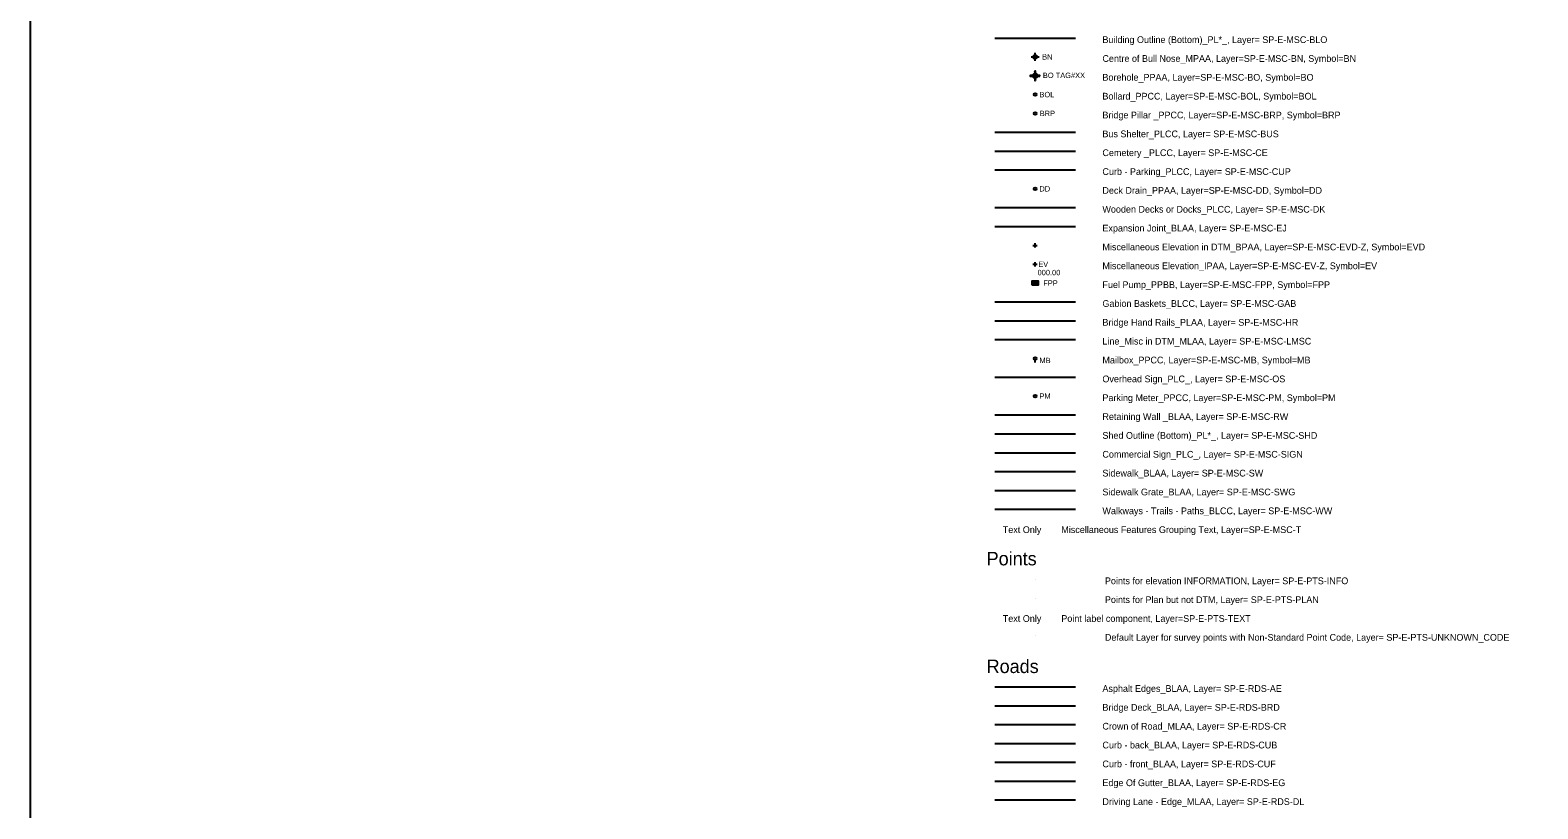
# Model space of a CAD drawing. Extents: x 500528 to 502626, y 4210261 to 4212624.
# Drawn here: x 500528 to 501088, y 4211439 to 4211729 of the extents above; entities that cross this region are included whole.
import ezdxf

# ---------------------------------------------------------------- set-up
doc = ezdxf.new("R2010")
doc.units = 0
for name, color, linetype in [('Default', 7, 'Continuous'), ('SP-E-MSC-BLO', 7, 'Continuous'), ('SP-E-MSC-BN', 7, 'Continuous'), ('SP-E-MSC-BO', 7, 'Continuous'), ('SP-E-MSC-BOL', 7, 'Continuous'), ('SP-E-MSC-BRP', 7, 'Continuous'), ('SP-E-MSC-BUS', 7, 'Continuous'), ('SP-E-MSC-CE', 7, 'Continuous'), ('SP-E-MSC-CUP', 7, 'Continuous'), ('SP-E-MSC-DD', 7, 'Continuous'), ('SP-E-MSC-DK', 7, 'Continuous'), ('SP-E-MSC-EJ', 7, 'Continuous'), ('SP-E-MSC-EV-Z', 7, 'Continuous'), ('SP-E-MSC-EVD-Z', 7, 'Continuous'), ('SP-E-MSC-FPP', 7, 'Continuous'), ('SP-E-MSC-GAB', 7, 'Continuous'), ('SP-E-MSC-HR', 7, 'Continuous'), ('SP-E-MSC-LMSC', 7, 'Continuous'), ('SP-E-MSC-MB', 7, 'Continuous'), ('SP-E-MSC-OS', 7, 'Continuous'), ('SP-E-MSC-PM', 7, 'Continuous'), ('SP-E-MSC-RW', 7, 'Continuous'), ('SP-E-MSC-SHD', 7, 'Continuous'), ('SP-E-MSC-SIGN', 7, 'Continuous'), ('SP-E-MSC-SW', 7, 'Continuous'), ('SP-E-MSC-SWG', 7, 'Continuous'), ('SP-E-MSC-T', 7, 'Continuous'), ('SP-E-MSC-WW', 7, 'Continuous'), ('SP-E-PTS-INFO', 7, 'Continuous'), ('SP-E-PTS-PLAN', 7, 'Continuous'), ('SP-E-PTS-TEXT', 7, 'Continuous'), ('SP-E-PTS-UNKNOWN_CODE', 7, 'Continuous'), ('SP-E-RDS-AE', 7, 'Continuous'), ('SP-E-RDS-BRD', 7, 'Continuous'), ('SP-E-RDS-CR', 7, 'Continuous'), ('SP-E-RDS-CUB', 7, 'Continuous'), ('SP-E-RDS-CUF', 7, 'Continuous'), ('SP-E-RDS-DL', 7, 'Continuous'), ('SP-E-RDS-EG', 7, 'Continuous')]:
    doc.layers.add(name, color=color, linetype=linetype)

# ---------------------------------------------------------------- blocks, each defined once
blk = doc.blocks.new('POINT_DISPLAY')
at = {"layer": 'Default'}
blk.add_line((0, 0), (0, 0), dxfattribs=at)
blk = doc.blocks.new('BN')
at = {"layer": 'SP-E-MSC-T'}
for points in [[(-0.15, 0), (0.15, 0)], [(0, -0.15), (0, 0.15)]]:
    blk.add_lwpolyline(points, dxfattribs=at)
blk.add_circle((0, 0), 0.075, dxfattribs=at)
at = {"layer": 'SP-E-MSC-BN'}
blk.add_blockref('POINT_DISPLAY', (0, 0), dxfattribs=at)
at = {"layer": 'SP-E-MSC-T'}
blk.add_text('BN', height=0.2, dxfattribs=at).set_placement((0.262, -0.1))
blk = doc.blocks.new('BO')
at = {"layer": 'SP-E-MSC-BO'}
for points in [[(0.174, 0.011), (-0.18, 0.011)], [(-0.18, 0.011), (-0.18, -0.011)], [(-0.087, 0.005), (-0.18, 0.011), (-0.18, 0.005), (-0.087, 0.005)], [(-0.087, 0.005), (-0.086, 0.011), (-0.18, 0.011), (-0.087, 0.005)], [(-0.087, 0), (-0.18, 0.005), (-0.18, 0), (-0.087, 0)], [(-0.087, 0), (-0.087, 0.005), (-0.18, 0.005), (-0.087, 0)], [(-0.087, -0.005), (-0.18, 0), (-0.18, -0.005), (-0.087, -0.005)], [(-0.087, -0.005), (-0.087, 0), (-0.18, 0), (-0.087, -0.005)], [(0.011, 0.166), (-0.011, 0.166)], [(-0.011, 0.166), (-0.011, -0.174)], [(0.011, 0.087), (-0.011, 0.166), (-0.011, 0.087), (0.011, 0.087)], [(0.011, 0.087), (0.011, 0.166), (-0.011, 0.166), (0.011, 0.087)], [(-0.011, 0.086), (0, 0.087), (-0.011, 0.087), (-0.011, 0.086)], [(0.011, 0.086), (0.011, 0.087), (0, 0.087), (0.011, 0.086)], [(0, 0), (0, 0)], [(0.011, -0.174), (0.011, 0.166)], [(0.174, 0.005), (0.086, 0.011), (0.087, 0.005), (0.174, 0.005)], [(0.174, 0.005), (0.174, 0.011), (0.086, 0.011), (0.174, 0.005)], [(0.174, 0), (0.087, 0.005), (0.087, 0), (0.174, 0)], [(0.174, 0), (0.174, 0.005), (0.087, 0.005), (0.174, 0)], [(0.174, -0.005), (0.087, 0), (0.087, -0.005), (0.174, -0.005)], [(0.174, -0.005), (0.174, 0), (0.087, 0), (0.174, -0.005)], [(0.174, -0.011), (0.174, 0.011)], [(-0.086, -0.011), (-0.18, -0.005), (-0.18, -0.011), (-0.086, -0.011)], [(-0.086, -0.011), (-0.087, -0.005), (-0.18, -0.005), (-0.086, -0.011)], [(-0.18, -0.011), (0.174, -0.011)], [(0, -0.087), (-0.011, -0.086), (-0.011, -0.087), (0, -0.087)], [(0.011, -0.174), (-0.011, -0.087), (-0.011, -0.174), (0.011, -0.174)], [(0.011, -0.174), (0.011, -0.087), (-0.011, -0.087), (0.011, -0.174)], [(-0.011, -0.174), (0.011, -0.174)], [(0.011, -0.087), (0.011, -0.086), (0, -0.087), (0.011, -0.087)], [(0.174, -0.011), (0.087, -0.005), (0.086, -0.011), (0.174, -0.011)], [(0.174, -0.011), (0.174, -0.005), (0.087, -0.005), (0.174, -0.011)]]:
    blk.add_lwpolyline(points, dxfattribs=at)
blk.add_circle((0, 0), 0.0871, dxfattribs=at)
at = {"layer": 'SP-E-MSC-T'}
blk.add_text('BO TAG#XX', height=0.2, dxfattribs=at).set_placement((0.289, -0.086))
blk = doc.blocks.new('BOL')
at = {"layer": 'SP-E-MSC-BOL'}
blk.add_lwpolyline([(0, 0), (0, 0)], dxfattribs=at)
blk.add_circle((0, 0), 0.05, dxfattribs=at)
at = {"layer": 'SP-E-MSC-T'}
blk.add_text('BOL', height=0.2, dxfattribs=at).set_placement((0.162, -0.1))
blk = doc.blocks.new('BRP')
at = {"layer": 'SP-E-MSC-BRP'}
blk.add_lwpolyline([(0, 0), (0, 0)], dxfattribs=at)
blk.add_circle((0, 0), 0.05, dxfattribs=at)
at = {"layer": 'SP-E-MSC-T'}
blk.add_text('BRP', height=0.2, dxfattribs=at).set_placement((0.171, -0.1))
blk = doc.blocks.new('DD')
at = {"layer": 'SP-E-MSC-DD'}
blk.add_lwpolyline([(0, 0), (0, 0)], dxfattribs=at)
blk.add_circle((0, 0), 0.05, dxfattribs=at)
at = {"layer": 'SP-E-MSC-T'}
blk.add_text('DD', height=0.2, dxfattribs=at).set_placement((0.162, -0.1))
blk = doc.blocks.new('EVD')
at = {"layer": 'SP-E-MSC-T'}
for points in [[(-0.08, 0), (0.08, 0)], [(0, -0.08), (0, 0.08)]]:
    blk.add_lwpolyline(points, dxfattribs=at)
at = {"layer": 'SP-E-MSC-EVD-Z'}
blk.add_blockref('POINT_DISPLAY', (0, 0), dxfattribs=at)
blk = doc.blocks.new('EV')
at = {"layer": 'SP-E-MSC-EV-Z'}
for points in [[(-0.08, 0), (0.08, 0)], [(0, -0.08), (0, 0.08)]]:
    blk.add_lwpolyline(points, dxfattribs=at)
at = {"layer": 'SP-E-MSC-T'}
for s, p in [('EV', (0.117, -0.1)), ('000.00', (0.092, -0.41))]:
    blk.add_text(s, height=0.2, dxfattribs=at).set_placement(p)
blk = doc.blocks.new('FPP')
at = {"layer": 'SP-E-MSC-FPP'}
for points in [[(-0.12, -0.065), (0.12, -0.065), (0.12, 0.065), (-0.12, 0.065), (-0.12, -0.065)], [(-0.059, -0.032), (0.059, -0.032), (0.059, 0.032), (-0.059, 0.032), (-0.059, -0.032)], [(0.059, 0.032), (-0.059, -0.032)], [(-0.059, 0.032), (0.059, -0.032)]]:
    blk.add_lwpolyline(points, dxfattribs=at)
at = {"layer": 'SP-E-MSC-T'}
blk.add_text('FPP', height=0.2, dxfattribs=at).set_placement((0.303, -0.1))
blk = doc.blocks.new('MB')
at = {"layer": 'SP-E-MSC-MB'}
for points in [[(0, 0), (0, 0)], [(0, -0.15), (0, -0.05)]]:
    blk.add_lwpolyline(points, dxfattribs=at)
blk.add_circle((0, 0), 0.0495, dxfattribs=at)
at = {"layer": 'SP-E-MSC-T'}
blk.add_text('MB', height=0.2, dxfattribs=at).set_placement((0.162, -0.175))
blk = doc.blocks.new('PM')
at = {"layer": 'SP-E-MSC-PM'}
blk.add_lwpolyline([(0, 0), (0, 0)], dxfattribs=at)
blk.add_circle((0, 0), 0.05, dxfattribs=at)
at = {"layer": 'SP-E-MSC-T'}
blk.add_text('PM', height=0.2, dxfattribs=at).set_placement((0.162, -0.1))

msp = doc.modelspace()

# ---------------------------------------------------------------- linework, layer by layer
at = {"layer": 'Default'}
msp.add_lwpolyline([(500528.35, 4212623.85), (500528.35, 4210260.5), (502626.48, 4210260.5), (502626.48, 4212623.85), (500528.35, 4212623.85)], dxfattribs=at)
msp.add_lwpolyline([(500528.35, 4210260.5), (502626.48, 4210260.5), (502626.48, 4212623.85), (500528.35, 4212623.85)], close=True, dxfattribs=at)
at = {"layer": 'SP-E-MSC-BLO'}
msp.add_line((500886.55, 4211725.59), (500916.55, 4211725.59), dxfattribs=at)
at = {"layer": 'SP-E-MSC-BUS'}
msp.add_line((500886.55, 4211690.59), (500916.55, 4211690.59), dxfattribs=at)
at = {"layer": 'SP-E-MSC-CE'}
msp.add_line((500886.55, 4211683.59), (500916.55, 4211683.59), dxfattribs=at)
at = {"layer": 'SP-E-MSC-CUP'}
msp.add_line((500886.55, 4211676.59), (500916.55, 4211676.59), dxfattribs=at)
at = {"layer": 'SP-E-MSC-DK'}
msp.add_line((500886.55, 4211662.59), (500916.55, 4211662.59), dxfattribs=at)
at = {"layer": 'SP-E-MSC-EJ'}
msp.add_line((500886.55, 4211655.59), (500916.55, 4211655.59), dxfattribs=at)
at = {"layer": 'SP-E-MSC-GAB'}
msp.add_line((500886.55, 4211627.59), (500916.55, 4211627.59), dxfattribs=at)
at = {"layer": 'SP-E-MSC-HR'}
msp.add_line((500886.55, 4211620.59), (500916.55, 4211620.59), dxfattribs=at)
at = {"layer": 'SP-E-MSC-LMSC'}
msp.add_line((500886.55, 4211613.59), (500916.55, 4211613.59), dxfattribs=at)
at = {"layer": 'SP-E-MSC-OS'}
msp.add_line((500886.55, 4211599.59), (500916.55, 4211599.59), dxfattribs=at)
at = {"layer": 'SP-E-MSC-RW'}
msp.add_line((500886.55, 4211585.59), (500916.55, 4211585.59), dxfattribs=at)
at = {"layer": 'SP-E-MSC-SHD'}
msp.add_line((500886.55, 4211578.59), (500916.55, 4211578.59), dxfattribs=at)
at = {"layer": 'SP-E-MSC-SIGN'}
msp.add_line((500886.55, 4211571.59), (500916.55, 4211571.59), dxfattribs=at)
at = {"layer": 'SP-E-MSC-SW'}
msp.add_line((500886.55, 4211564.59), (500916.55, 4211564.59), dxfattribs=at)
at = {"layer": 'SP-E-MSC-SWG'}
msp.add_line((500886.55, 4211557.59), (500916.55, 4211557.59), dxfattribs=at)
at = {"layer": 'SP-E-MSC-WW'}
msp.add_line((500886.55, 4211550.59), (500916.55, 4211550.59), dxfattribs=at)
at = {"layer": 'SP-E-RDS-AE'}
msp.add_line((500886.55, 4211484.59), (500916.55, 4211484.59), dxfattribs=at)
at = {"layer": 'SP-E-RDS-BRD'}
msp.add_line((500886.55, 4211477.59), (500916.55, 4211477.59), dxfattribs=at)
at = {"layer": 'SP-E-RDS-CR'}
msp.add_line((500886.55, 4211470.59), (500916.55, 4211470.59), dxfattribs=at)
at = {"layer": 'SP-E-RDS-CUB'}
msp.add_line((500886.55, 4211463.59), (500916.55, 4211463.59), dxfattribs=at)
at = {"layer": 'SP-E-RDS-CUF'}
msp.add_line((500886.55, 4211456.59), (500916.55, 4211456.59), dxfattribs=at)
at = {"layer": 'SP-E-RDS-DL'}
msp.add_line((500886.55, 4211442.59), (500916.55, 4211442.59), dxfattribs=at)
at = {"layer": 'SP-E-RDS-EG'}
msp.add_line((500886.55, 4211449.59), (500916.55, 4211449.59), dxfattribs=at)

# ---------------------------------------------------------------- block references
at = {"layer": 'SP-E-MSC-BN', "xscale": 10, "yscale": 10}
msp.add_blockref('BN', (500901.55, 4211718.59), dxfattribs=at)
at = {"layer": 'SP-E-MSC-BO', "xscale": 10, "yscale": 10}
msp.add_blockref('BO', (500901.55, 4211711.59), dxfattribs=at)
at = {"layer": 'SP-E-MSC-BOL', "xscale": 10, "yscale": 10}
msp.add_blockref('BOL', (500901.55, 4211704.59), dxfattribs=at)
at = {"layer": 'SP-E-MSC-BRP', "xscale": 10, "yscale": 10}
msp.add_blockref('BRP', (500901.55, 4211697.59), dxfattribs=at)
at = {"layer": 'SP-E-MSC-DD', "xscale": 10, "yscale": 10}
msp.add_blockref('DD', (500901.55, 4211669.59), dxfattribs=at)
at = {"layer": 'SP-E-MSC-EV-Z', "xscale": 10, "yscale": 10}
msp.add_blockref('EV', (500901.55, 4211641.59), dxfattribs=at)
at = {"layer": 'SP-E-MSC-EVD-Z', "xscale": 10, "yscale": 10}
msp.add_blockref('EVD', (500901.55, 4211648.59), dxfattribs=at)
at = {"layer": 'SP-E-MSC-FPP', "xscale": 10, "yscale": 10}
msp.add_blockref('FPP', (500901.55, 4211634.59), dxfattribs=at)
at = {"layer": 'SP-E-MSC-MB', "xscale": 10, "yscale": 10}
msp.add_blockref('MB', (500901.55, 4211606.59), dxfattribs=at)
at = {"layer": 'SP-E-MSC-PM', "xscale": 10, "yscale": 10}
msp.add_blockref('PM', (500901.55, 4211592.59), dxfattribs=at)
at = {"layer": 'SP-E-PTS-INFO', "xscale": 10, "yscale": 10}
msp.add_blockref('POINT_DISPLAY', (500901.55, 4211524.59), dxfattribs=at)
at = {"layer": 'SP-E-PTS-PLAN', "xscale": 10, "yscale": 10}
msp.add_blockref('POINT_DISPLAY', (500901.55, 4211517.59), dxfattribs=at)
at = {"layer": 'SP-E-PTS-UNKNOWN_CODE', "xscale": 10, "yscale": 10}
msp.add_blockref('POINT_DISPLAY', (500901.55, 4211503.59), dxfattribs=at)

# ---------------------------------------------------------------- texts
at = {"layer": 'Default'}
for s, p in [('Points ', (500883.55, 4211529.74)), ('Roads ', (500883.55, 4211489.74))]:
    msp.add_text(s, height=5, dxfattribs=at).set_placement(p)
at = {"layer": 'SP-E-MSC-BLO'}
msp.add_text('Building Outline (Bottom)_PL*_, Layer= SP-E-MSC-BLO ', height=2.5, dxfattribs=at).set_placement((500926.55, 4211723.74))
at = {"layer": 'SP-E-MSC-BN'}
msp.add_text('Centre of Bull Nose_MPAA, Layer=SP-E-MSC-BN, Symbol=BN ', height=2.5, dxfattribs=at).set_placement((500926.55, 4211716.74))
at = {"layer": 'SP-E-MSC-BO'}
msp.add_text('Borehole_PPAA, Layer=SP-E-MSC-BO, Symbol=BO ', height=2.5, dxfattribs=at).set_placement((500926.55, 4211709.74))
at = {"layer": 'SP-E-MSC-BOL'}
msp.add_text('Bollard_PPCC, Layer=SP-E-MSC-BOL, Symbol=BOL ', height=2.5, dxfattribs=at).set_placement((500926.55, 4211702.74))
at = {"layer": 'SP-E-MSC-BRP'}
msp.add_text('Bridge Pillar _PPCC, Layer=SP-E-MSC-BRP, Symbol=BRP ', height=2.5, dxfattribs=at).set_placement((500926.55, 4211695.74))
at = {"layer": 'SP-E-MSC-BUS'}
msp.add_text('Bus Shelter_PLCC, Layer= SP-E-MSC-BUS ', height=2.5, dxfattribs=at).set_placement((500926.55, 4211688.74))
at = {"layer": 'SP-E-MSC-CE'}
msp.add_text('Cemetery _PLCC, Layer= SP-E-MSC-CE ', height=2.5, dxfattribs=at).set_placement((500926.55, 4211681.74))
at = {"layer": 'SP-E-MSC-CUP'}
msp.add_text('Curb - Parking_PLCC, Layer= SP-E-MSC-CUP ', height=2.5, dxfattribs=at).set_placement((500926.55, 4211674.74))
at = {"layer": 'SP-E-MSC-DD'}
msp.add_text('Deck Drain_PPAA, Layer=SP-E-MSC-DD, Symbol=DD ', height=2.5, dxfattribs=at).set_placement((500926.55, 4211667.74))
at = {"layer": 'SP-E-MSC-DK'}
msp.add_text('Wooden Decks or Docks_PLCC, Layer= SP-E-MSC-DK ', height=2.5, dxfattribs=at).set_placement((500926.55, 4211660.74))
at = {"layer": 'SP-E-MSC-EJ'}
msp.add_text('Expansion Joint_BLAA, Layer= SP-E-MSC-EJ ', height=2.5, dxfattribs=at).set_placement((500926.55, 4211653.74))
at = {"layer": 'SP-E-MSC-EV-Z'}
msp.add_text('Miscellaneous Elevation_IPAA, Layer=SP-E-MSC-EV-Z, Symbol=EV ', height=2.5, dxfattribs=at).set_placement((500926.55, 4211639.74))
at = {"layer": 'SP-E-MSC-EVD-Z'}
msp.add_text('Miscellaneous Elevation in DTM_BPAA, Layer=SP-E-MSC-EVD-Z, Symbol=EVD ', height=2.5, dxfattribs=at).set_placement((500926.55, 4211646.74))
at = {"layer": 'SP-E-MSC-FPP'}
msp.add_text('Fuel Pump_PPBB, Layer=SP-E-MSC-FPP, Symbol=FPP ', height=2.5, dxfattribs=at).set_placement((500926.55, 4211632.74))
at = {"layer": 'SP-E-MSC-GAB'}
msp.add_text('Gabion Baskets_BLCC, Layer= SP-E-MSC-GAB ', height=2.5, dxfattribs=at).set_placement((500926.55, 4211625.74))
at = {"layer": 'SP-E-MSC-HR'}
msp.add_text('Bridge Hand Rails_PLAA, Layer= SP-E-MSC-HR ', height=2.5, dxfattribs=at).set_placement((500926.55, 4211618.74))
at = {"layer": 'SP-E-MSC-LMSC'}
msp.add_text('Line_Misc in DTM_MLAA, Layer= SP-E-MSC-LMSC ', height=2.5, dxfattribs=at).set_placement((500926.55, 4211611.74))
at = {"layer": 'SP-E-MSC-MB'}
msp.add_text('Mailbox_PPCC, Layer=SP-E-MSC-MB, Symbol=MB ', height=2.5, dxfattribs=at).set_placement((500926.55, 4211604.74))
at = {"layer": 'SP-E-MSC-OS'}
msp.add_text('Overhead Sign_PLC_, Layer= SP-E-MSC-OS ', height=2.5, dxfattribs=at).set_placement((500926.55, 4211597.74))
at = {"layer": 'SP-E-MSC-PM'}
msp.add_text('Parking Meter_PPCC, Layer=SP-E-MSC-PM, Symbol=PM ', height=2.5, dxfattribs=at).set_placement((500926.55, 4211590.74))
at = {"layer": 'SP-E-MSC-RW'}
msp.add_text('Retaining Wall _BLAA, Layer= SP-E-MSC-RW ', height=2.5, dxfattribs=at).set_placement((500926.55, 4211583.74))
at = {"layer": 'SP-E-MSC-SHD'}
msp.add_text('Shed Outline (Bottom)_PL*_, Layer= SP-E-MSC-SHD ', height=2.5, dxfattribs=at).set_placement((500926.55, 4211576.74))
at = {"layer": 'SP-E-MSC-SIGN'}
msp.add_text('Commercial Sign_PLC_, Layer= SP-E-MSC-SIGN ', height=2.5, dxfattribs=at).set_placement((500926.55, 4211569.74))
at = {"layer": 'SP-E-MSC-SW'}
msp.add_text('Sidewalk_BLAA, Layer= SP-E-MSC-SW ', height=2.5, dxfattribs=at).set_placement((500926.55, 4211562.74))
at = {"layer": 'SP-E-MSC-SWG'}
msp.add_text('Sidewalk Grate_BLAA, Layer= SP-E-MSC-SWG ', height=2.5, dxfattribs=at).set_placement((500926.55, 4211555.74))
at = {"layer": 'SP-E-MSC-T'}
msp.add_text('Text Only        Miscellaneous Features Grouping Text, Layer=SP-E-MSC-T', height=2.5, dxfattribs=at).set_placement((500889.55, 4211541.74))
at = {"layer": 'SP-E-MSC-WW'}
msp.add_text('Walkways - Trails - Paths_BLCC, Layer= SP-E-MSC-WW ', height=2.5, dxfattribs=at).set_placement((500926.55, 4211548.74))
at = {"layer": 'SP-E-PTS-INFO'}
msp.add_text(' Points for elevation INFORMATION, Layer= SP-E-PTS-INFO ', height=2.5, dxfattribs=at).set_placement((500926.55, 4211522.74))
at = {"layer": 'SP-E-PTS-PLAN'}
msp.add_text(' Points for Plan but not DTM, Layer= SP-E-PTS-PLAN ', height=2.5, dxfattribs=at).set_placement((500926.55, 4211515.74))
at = {"layer": 'SP-E-PTS-TEXT'}
msp.add_text('Text Only        Point label component, Layer=SP-E-PTS-TEXT', height=2.5, dxfattribs=at).set_placement((500889.55, 4211508.74))
at = {"layer": 'SP-E-PTS-UNKNOWN_CODE'}
msp.add_text(' Default Layer for survey points with Non-Standard Point Code, Layer= SP-E-PTS-UNKNOWN_CODE ', height=2.5, dxfattribs=at).set_placement((500926.55, 4211501.74))
at = {"layer": 'SP-E-RDS-AE'}
msp.add_text('Asphalt Edges_BLAA, Layer= SP-E-RDS-AE ', height=2.5, dxfattribs=at).set_placement((500926.55, 4211482.74))
at = {"layer": 'SP-E-RDS-BRD'}
msp.add_text('Bridge Deck_BLAA, Layer= SP-E-RDS-BRD ', height=2.5, dxfattribs=at).set_placement((500926.55, 4211475.74))
at = {"layer": 'SP-E-RDS-CR'}
msp.add_text('Crown of Road_MLAA, Layer= SP-E-RDS-CR ', height=2.5, dxfattribs=at).set_placement((500926.55, 4211468.74))
at = {"layer": 'SP-E-RDS-CUB'}
msp.add_text('Curb - back_BLAA, Layer= SP-E-RDS-CUB ', height=2.5, dxfattribs=at).set_placement((500926.55, 4211461.74))
at = {"layer": 'SP-E-RDS-CUF'}
msp.add_text('Curb - front_BLAA, Layer= SP-E-RDS-CUF ', height=2.5, dxfattribs=at).set_placement((500926.55, 4211454.74))
at = {"layer": 'SP-E-RDS-DL'}
msp.add_text('Driving Lane - Edge_MLAA, Layer= SP-E-RDS-DL ', height=2.5, dxfattribs=at).set_placement((500926.55, 4211440.74))
at = {"layer": 'SP-E-RDS-EG'}
msp.add_text('Edge Of Gutter_BLAA, Layer= SP-E-RDS-EG ', height=2.5, dxfattribs=at).set_placement((500926.55, 4211447.74))

doc.saveas('drawing.dxf')
